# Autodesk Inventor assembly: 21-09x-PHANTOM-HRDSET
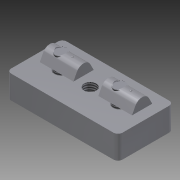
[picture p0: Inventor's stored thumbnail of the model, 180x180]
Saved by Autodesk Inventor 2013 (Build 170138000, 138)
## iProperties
Created: 2004-11
Part Number: 21-09x-PHANTOM-HRDSET
Document SubType Name: Assembly
Designer: Autodesk, Inc.
Manufacturer: Standard
Standards Organization: Custom
Description: PHANTOM, CASTER MOUNT, HARDWARE SET
Catalog Web Link: http://www.parker.com/ead/cm1.asp?cmid=809
Vendor: PARKER IPS
Mass: 363.595 g
Surface Area: 145.111 cm^2
Volume: 46.3769 cm^3
Density: 7.84 g/cm^3
CAGE: 1LJX3
Dept. ID: Product Design
Description #2: ---
Finish #1: ---
Finish #2: ---
Material ID: ---
Project Number: ---
Author: Autodesk, Inc.
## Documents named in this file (7)
- Z:\_DATEN\Test Station\Components\21-09x_Caster_Mnt_Phantom.iam
- Z:\_DATEN\Test Station\Components\24-118-8.ipt
- Z:\_DATEN\Test Station\Components\21-002.ipt
- Z:\_DATEN\Test Station\Components\20-058.ipt
- C:\Users\kelleyb.ADS\Desktop\Samples MIGRATED 2009 224 RTM_1\Standard Parts\Test Station Content\Fastners\2X-YYY-ZZ IPS Screws.ipt
- C:\Users\kelleyb.ADS\Desktop\Samples MIGRATED 2009 224 RTM_1\Standard Parts\Test Station Content\Corners, Gussets, and Mounting Plates\21-XXX Mounting Plates.ipt
- C:\Users\kelleyb.ADS\Desktop\Samples MIGRATED 2009 224 RTM_1\Standard Parts\Test Station Content\Fastners\20-XXX TSlot Nuts.ipt
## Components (5 placed, 3 different names)
1. 24-118-8:1
2. 24-118-8:2
3. 21-002:1
4. 20-058:1
5. 20-058:2
